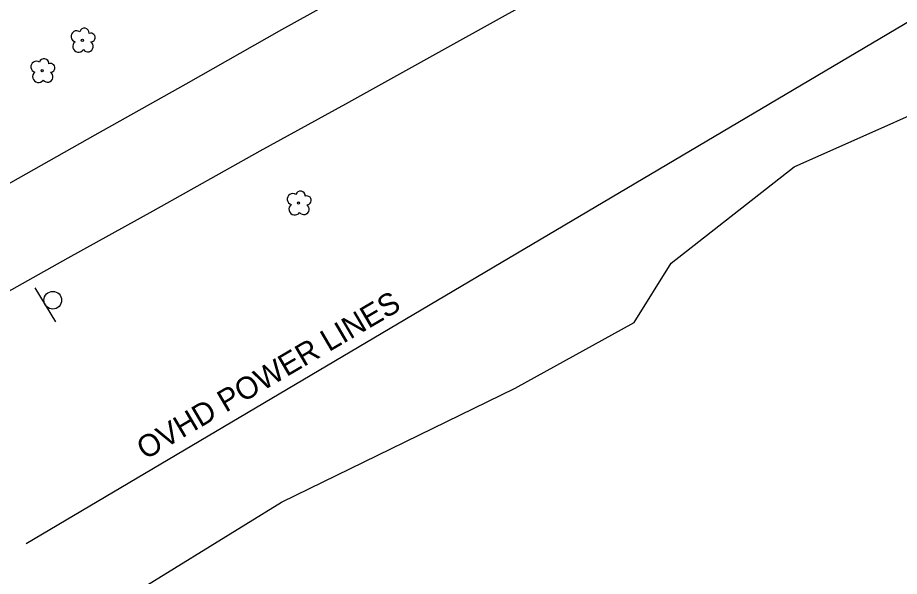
# Model space of a CAD drawing. Extents: x 2076109 to 2080761, y 592812 to 596750.
# Drawn here: x 2077526.3 to 2077726, y 595822.6 to 595949.2 of the extents above; entities that cross this region are included whole.
import ezdxf

# ---------------------------------------------------------------- set-up
doc = ezdxf.new("R2010")
doc.units = 0
for name, color, linetype in [('Default', 7, 'Continuous'), ('RD_EX_BldgApp', 7, 'Continuous'), ('RD_EX_Road', 7, 'Continuous'), ('RD_EX_UT', 7, 'Continuous'), ('RD_EX_UT_txCode', 7, 'Continuous'), ('RD_EX_VEG', 7, 'Continuous')]:
    doc.layers.add(name, color=color, linetype=linetype)

msp = doc.modelspace()

# ---------------------------------------------------------------- linework, layer by layer
at = {"layer": 'Default'}
msp.add_arc((2035586.7, 547847.96), 63546.51, 48.5011873, 49.2923126, dxfattribs=at)
msp.add_arc((2035586.7, 547847.96), 63546.51, 48.5011873, 49.2923126, dxfattribs=at)
at = {"layer": 'RD_EX_BldgApp'}
msp.add_line((2077530.18, 595888), (2077534.86, 595880.31), dxfattribs=at)
msp.add_line((2077530.18, 595888), (2077534.86, 595880.31), dxfattribs=at)
msp.add_circle((2077534.26, 595885.19), 2, dxfattribs=at)
msp.add_circle((2077534.26, 595885.19), 2, dxfattribs=at)
at = {"layer": 'RD_EX_Road'}
for points in [[(2077772.92, 596058.93), (2077769.46, 596053.64), (2077765.13, 596047.65), (2077751.94, 596040.06), (2077734.63, 596030.03), (2077714.84, 596018.75), (2077688.54, 596003.96), (2077665.9, 595991.28), (2077650.73, 595982.79), (2077619.31, 595965.17), (2077602.41, 595955.62), (2077586.04, 595946.49), (2077564.37, 595934.19), (2077543.8, 595922.59), (2077519.41, 595908.81)], [(2077772.92, 596058.93), (2077769.46, 596053.64), (2077765.13, 596047.65), (2077751.94, 596040.06), (2077734.63, 596030.03), (2077714.84, 596018.75), (2077688.54, 596003.96), (2077665.9, 595991.28), (2077650.73, 595982.79), (2077619.31, 595965.17), (2077602.41, 595955.62), (2077586.04, 595946.49), (2077564.37, 595934.19), (2077543.8, 595922.59), (2077519.41, 595908.81)], [(2077518.22, 595883.81), (2077537.74, 595894.82), (2077556.96, 595905.48), (2077581.25, 595919.03), (2077600.67, 595929.66), (2077624.41, 595942.93), (2077641.71, 595952.51), (2077666.01, 595966.53), (2077691.07, 595980.62), (2077718.14, 595995.67), (2077738.13, 596006.73)], [(2077518.22, 595883.81), (2077537.74, 595894.82), (2077556.96, 595905.48), (2077581.25, 595919.03), (2077600.67, 595929.66), (2077624.41, 595942.93), (2077641.71, 595952.51), (2077666.01, 595966.53), (2077691.07, 595980.62), (2077718.14, 595995.67), (2077738.13, 596006.73)]]:
    msp.add_lwpolyline(points, dxfattribs=at)
at = {"layer": 'RD_EX_UT'}
msp.add_line((2077528.24, 595830.07), (2077894.89, 596047.18), dxfattribs=at)
msp.add_line((2077528.24, 595830.07), (2077894.89, 596047.18), dxfattribs=at)
at = {"layer": 'RD_EX_VEG'}
msp.add_lwpolyline([(2077537.58, 595809.49), (2077586.06, 595839.41), (2077638.97, 595865.22), (2077665.91, 595880.11), (2077674.35, 595893.56), (2077702.2, 595915.39), (2077747.99, 595935.83), (2077759.3, 595943.54), (2077763.8, 595946.9), (2077769.61, 595946.39), (2077776.15, 595940.86), (2077771.62, 595922.27), (2077750.18, 595876.07), (2077738.76, 595842.17), (2077732.42, 595797.53)], dxfattribs=at)
msp.add_lwpolyline([(2077537.58, 595809.49), (2077586.06, 595839.41), (2077638.97, 595865.22), (2077665.91, 595880.11), (2077674.35, 595893.56), (2077702.2, 595915.39), (2077747.99, 595935.83), (2077759.3, 595943.54), (2077763.8, 595946.9), (2077769.61, 595946.39), (2077776.15, 595940.86), (2077771.62, 595922.27), (2077750.18, 595876.07), (2077738.76, 595842.17), (2077732.42, 595797.53)], dxfattribs=at)
for centre in [(2077540.97, 595944.1), (2077540.97, 595944.1), (2077531.85, 595937.21), (2077531.85, 595937.21), (2077589.91, 595907.2), (2077589.91, 595907.2)]:
    msp.add_circle(centre, 0.25, dxfattribs=at)
for centre, radius, start, end in [((2077539.67, 595944.99), 1.26, 56.211, 254.4932), ((2077539.67, 595944.99), 1.26, 56.211, 254.4932), ((2077541.42, 595945.75), 1.08, 354.7355, 164.5153), ((2077541.42, 595945.75), 1.08, 354.7355, 164.5153), ((2077540.12, 595942.72), 1.32, 126.6419, 325.5182), ((2077540.12, 595942.72), 1.32, 126.6419, 325.5182), ((2077542.19, 595942.7), 1.22, 216.3259, 57.8639), ((2077542.19, 595942.7), 1.22, 216.3259, 57.8639), ((2077542.86, 595944.72), 0.995, 268.5218, 111.806), ((2077542.86, 595944.72), 0.995, 268.5218, 111.806), ((2077532.3, 595938.86), 1.08, 354.7355, 164.5153), ((2077532.3, 595938.86), 1.08, 354.7355, 164.5153), ((2077530.56, 595938.11), 1.26, 56.211, 254.4932), ((2077530.56, 595938.11), 1.26, 56.211, 254.4932), ((2077533.75, 595937.84), 0.995, 268.5218, 111.806), ((2077533.75, 595937.84), 0.995, 268.5218, 111.806), ((2077531.01, 595935.84), 1.32, 126.6419, 325.5182), ((2077531.01, 595935.84), 1.32, 126.6419, 325.5182), ((2077533.08, 595935.81), 1.22, 216.3259, 57.8639), ((2077533.08, 595935.81), 1.22, 216.3259, 57.8639), ((2077590.36, 595908.85), 1.08, 354.7355, 164.5153), ((2077590.36, 595908.85), 1.08, 354.7355, 164.5153), ((2077588.62, 595908.09), 1.26, 56.211, 254.4932), ((2077588.62, 595908.09), 1.26, 56.211, 254.4932), ((2077591.81, 595907.82), 0.995, 268.5218, 111.806), ((2077591.81, 595907.82), 0.995, 268.5218, 111.806), ((2077589.07, 595905.82), 1.32, 126.6419, 325.5182), ((2077589.07, 595905.82), 1.32, 126.6419, 325.5182), ((2077591.13, 595905.8), 1.22, 216.3259, 57.8639), ((2077591.13, 595905.8), 1.22, 216.3259, 57.8639)]:
    msp.add_arc(centre, radius, start, end, dxfattribs=at)

# ---------------------------------------------------------------- texts
at = {"layer": 'RD_EX_UT_txCode'}
msp.add_text('OVHD POWER LINES', height=5, rotation=30.458, dxfattribs=at).set_placement((2077555.18, 595848.92))
msp.add_text('OVHD POWER LINES', height=5, rotation=30.458, dxfattribs=at).set_placement((2077555.18, 595848.92))

doc.saveas('drawing.dxf')
